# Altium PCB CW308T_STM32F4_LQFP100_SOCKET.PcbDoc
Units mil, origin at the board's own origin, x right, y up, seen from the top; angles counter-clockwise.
Board outline 2060 x 2540 mil, 2 copper layers (Top Layer, Bottom Layer); 21 components, 33 nets, 210 pads, 75 vias.
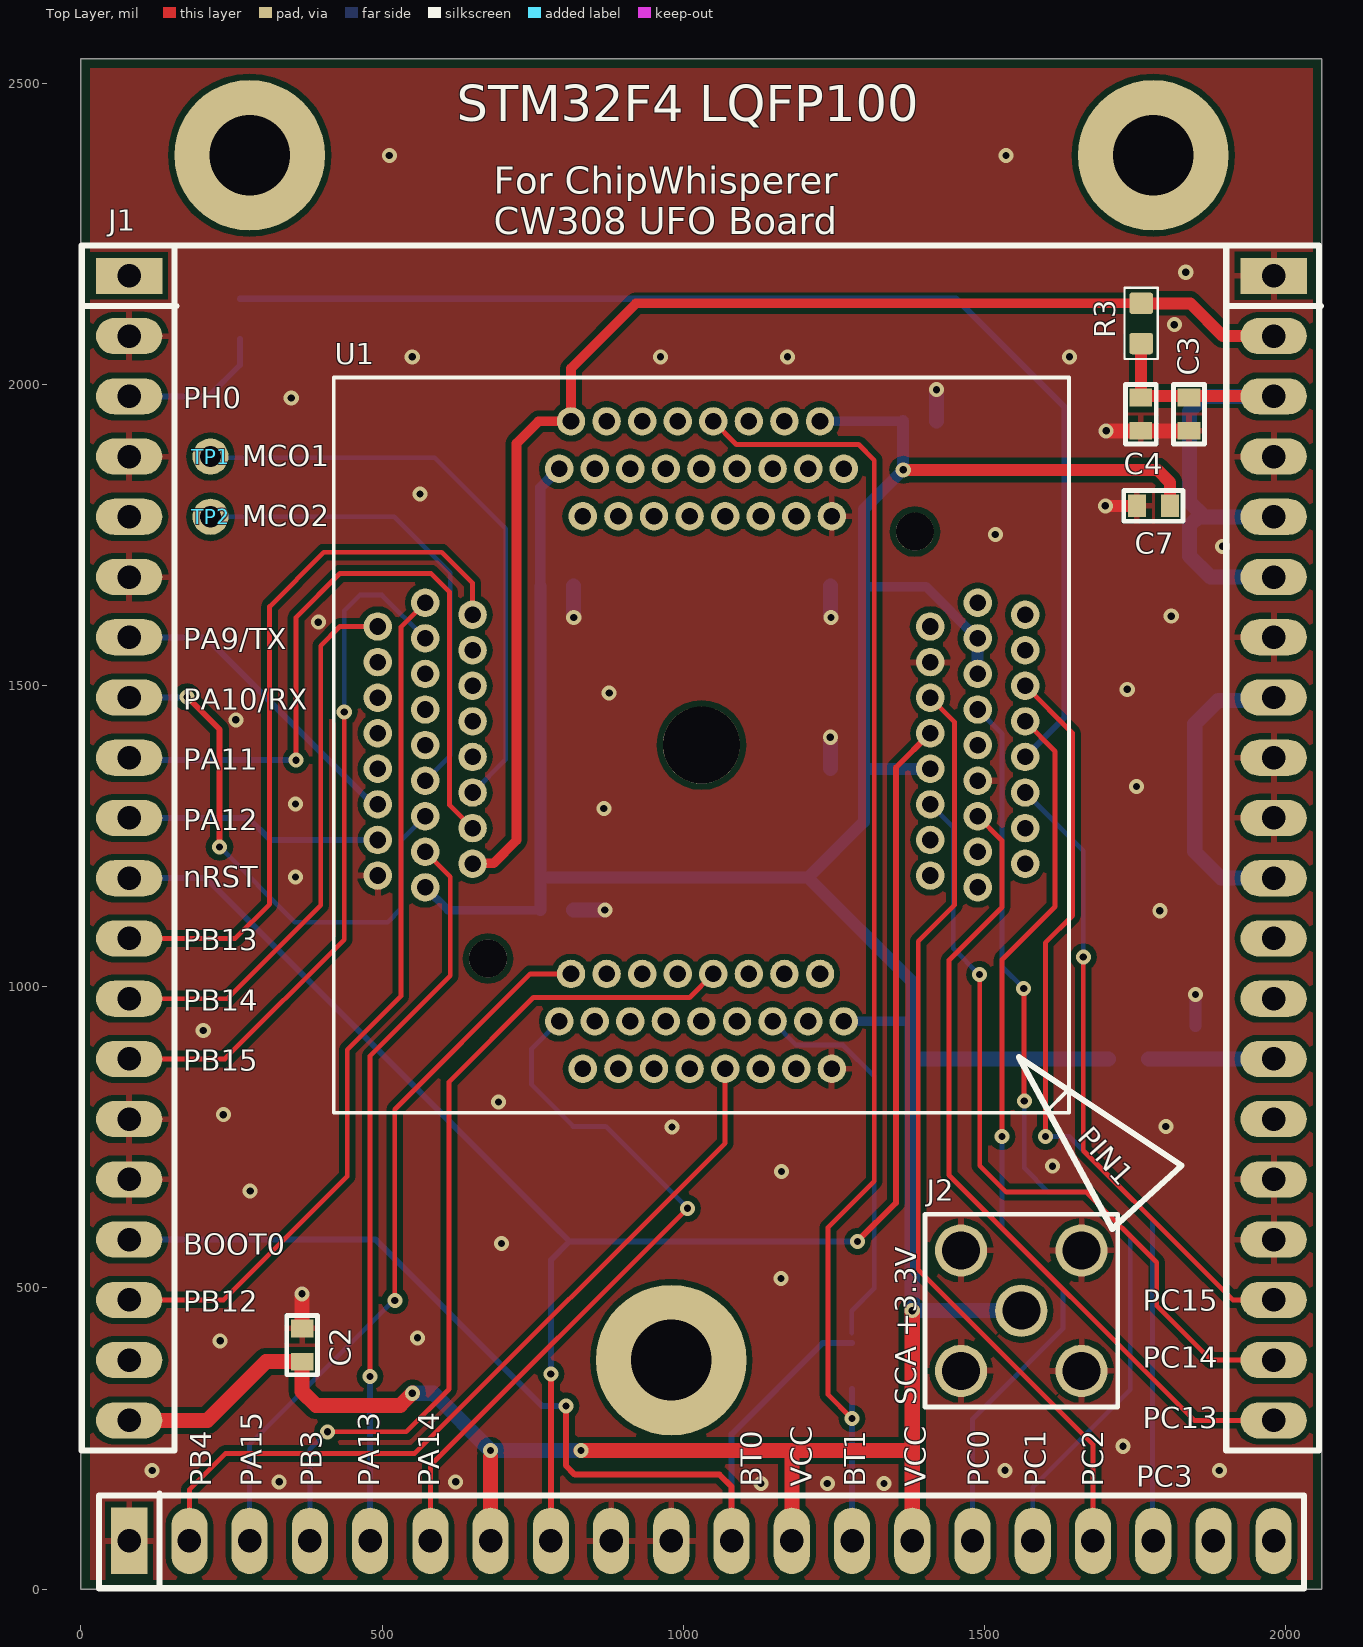
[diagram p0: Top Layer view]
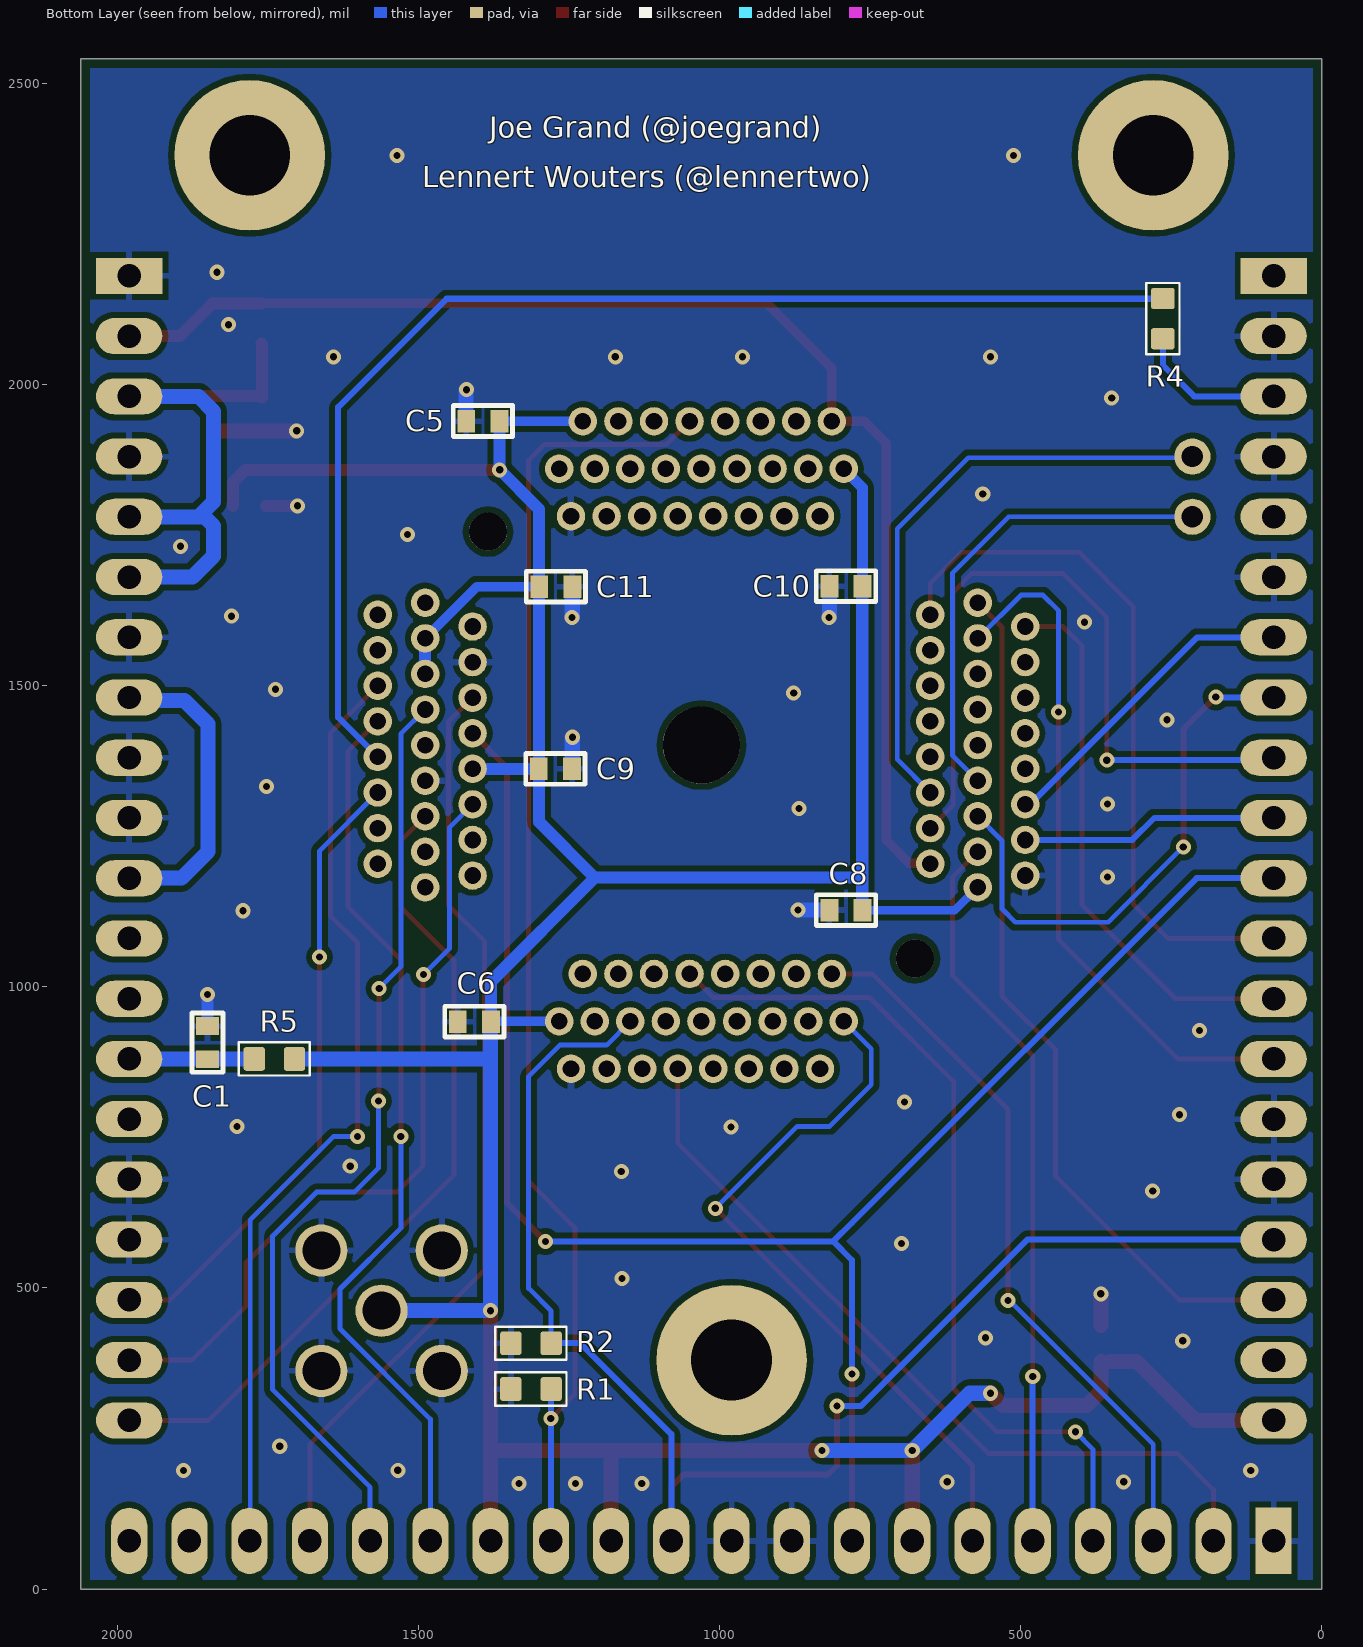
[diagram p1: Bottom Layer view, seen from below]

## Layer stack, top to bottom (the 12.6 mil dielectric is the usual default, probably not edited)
Top Solder: solder mask 0.4, Solder Resist, Dk 3.5
Top Layer: signal copper 1.4
Dielectric 1: dielectric 12.6, FR-4, Dk 4.8
Bottom Layer: signal copper 1.4
Bottom Solder: solder mask 0.4, Solder Resist, Dk 3.5

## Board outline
0,0 2060,0 2060,2540 0,2540

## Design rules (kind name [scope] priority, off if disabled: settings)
BoardOutlineClearance [All] p1: gap=15 ignorepadtopadclearanceinfootprint=FALSE except(0: Arc-SplitContinuation Track-SplitContinuation SMDPad-SplitContinuation THPad-SplitContinuation Via-SplitContinuation Fill-SplitContinuation Poly-SplitContinuation Region-SplitContinuation Text-SplitContinuation)
Clearance Clearance_1 [InPolygon] p1: gap=10 ignorepadtopadclearanceinfootprint=FALSE
Clearance [All] p2: gap=6 ignorepadtopadclearanceinfootprint=FALSE except(0: Arc-Hole Track-Hole SMDPad-Hole THPad-Hole Via-Hole Fill-Hole Poly-Hole Region-Hole Text-Hole)
HoleSize [All] p1: absolutevalues=TRUE maxlimit=200 minlimit=1 maxpercent=80.000 minpercent=20.000
MinimumSolderMaskSliver [All] p1: minsoldermaskwidth=5
PasteMaskExpansion PasteMaskExpansion_SJ [InComponent('SJ2')] p1: expansion=-200 // Disable SJ shorts
PasteMaskExpansion PasteMaskExpansion_TQFP [InComponent('U1')] p2: expansion=-1.5
PasteMaskExpansion [All] p3: expansion=0
PlaneConnect PlaneConnect_viaDirect [IsVia] p1: planeconnectstyle=Direct reliefexpansion=20 reliefentries=4 reliefconductorwidth=10 reliefairgap=10
PlaneConnect [All] p2: planeconnectstyle=Relief reliefexpansion=20 reliefentries=4 reliefconductorwidth=10 reliefairgap=10
PolygonConnect PolygonConnect_viaDirect [All vs isVia] p1: connectstyle=Direct reliefconductorwidth=10 reliefentries=4 polygonreliefangle="90 Angle" airgapwidth=10
PolygonConnect [All] p2: connectstyle=Relief reliefconductorwidth=10 reliefentries=4 polygonreliefangle="90 Angle" airgapwidth=10
RoutingVias [All] p1: holewidth=12 width=25 viastyle="Through Hole" minholewidth=12 minwidth=25 maxholewidth=28 maxwidth=50
SilkToSilkClearance [All] p1: silktosilkclearance=5
SilkToSolderMaskClearance [IsPad] p1: minsilkscreentomaskgap=2.9 clearancetoexposedcopper=TRUE
SolderMaskExpansion [All] p1: expansion=4 istentingtop=FALSE
SupplyNets "Schematic Supply Nets_1" [InNet('VCC')] p1: voltage=0.000
SupplyNets "Schematic Supply Nets" [InNet('GND')] p2: voltage=0.000
Width [All] p1: maxlimit=100 minlimit=6 preferedwidth=8 minimp=50.000000 maximp=50.000000 favimp=50.000000
24 further rules are at their usual default settings.

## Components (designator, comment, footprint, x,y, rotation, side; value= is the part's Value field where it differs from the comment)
C1 "100n" CAPC0603_M 1850,907 r90 bottom
C2 "100n" CAPC0603_M 367,405 r90 top
C3 "2u2" CAPC0603_M 1839.44,1950.25 r270 top
C4 "100n" CAPC0603_M 1759.44,1950.25 r270 top
C5 "100n" CAPC0603_M 1393,1939 r0 bottom
C6 "100n" CAPC0603_M 1407,942 r0 bottom
C7 "100n" CAPC0603_M 1780.44,1798.25 r180 top
C8 "100n" CAPC0603_M 790,1127 r0 bottom
C9 "100n" CAPC0603_M 1272.37,1361.63 r180 bottom
C10 "100n" CAPC0603_M 790,1665 r0 bottom
C11 "100n" CAPC0603_M 1271.81,1664.18 r180 bottom
J1 "CW308_TARGETCON" CW308_TBOARD_CONN 80,2180 r0 top locked
J2 "32K101-400L5" 32K101-400L5 1561,462 r0 top
R1 "10k" RESC1608X55N 1313,332 r0 bottom
R2 "10k" RESC1608X55N 1313,408 r0 bottom
R3 "10R" RESC1608X55N 1760,2101 r270 top
R4 "51R" RESC1608X55N 264,2109 r270 bottom value=100R
R5 "10R" RESC1608X55N 1739,880 r180 bottom
TP1 "TESTPOINT" TESTPOINT#1 215,1881 r0 top
TP2 "TESTPOINT" TESTPOINT#2 215,1780 r0 top
U1 "ALLSOCKET QFP100-0.5-STP" ALLSOCKET-QFP100 1030,1401 r0 top locked

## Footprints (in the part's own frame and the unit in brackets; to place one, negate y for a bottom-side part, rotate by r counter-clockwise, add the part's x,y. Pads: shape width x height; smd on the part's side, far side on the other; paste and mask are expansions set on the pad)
32K101-400L5 [mm] "Connector, SMA Jack, Vertical, 50 ohm, PCB mount"
  round 2.2 hole 1.6: 1(0,0) MP(-2.54,-2.54) MP(-2.54,2.54) MP(2.54,-2.54) MP(2.54,2.54)
  silkscreen extent -4.06,-4.06 4.06,4.06
ALLSOCKET-QFP100 [mm] "Thin QFP, 100-Leads, Body 14x14mm, Pitch 0.5mm, IPC Medium Density"
  round 1.2 hole 0.7 paste-2539.97 mask+0: 1(11.65,-6) 2(9.65,-5.5) 3(13.65,-5) 4(11.65,-4.5) 5(9.65,-4) 6(13.65,-3.5) 7(11.65,-3) 8(9.65,-2.5) 9(13.65,-2) 10(11.65,-1.5) 11(9.65,-1) 12(13.65,-0.5) 13(11.65,0) 14(9.65,0.5) 15(13.65,1) 16(11.65,1.5) 17(9.65,2) 18(13.65,2.5) 19(11.65,3) 20(9.65,3.5) 21(13.65,4) 22(11.65,4.5) 23(9.65,5) 24(13.65,5.5) 25(11.65,6) 26(6,11.65) 27(5.5,9.65) 28(5,13.65) 29(4.5,11.65) 30(4,9.65) 31(3.5,13.65) 32(3,11.65) 33(2.5,9.65) 34(2,13.65) 35(1.5,11.65) 36(1,9.65) 37(0.5,13.65) 38(0,11.65) 39(-0.5,9.65) 40(-1,13.65) 41(-1.5,11.65) 42(-2,9.65) 43(-2.5,13.65) 44(-3,11.65) 45(-3.5,9.65) 46(-4,13.65) 47(-4.5,11.65) 48(-5,9.65) 49(-5.5,13.65) 50(-6,11.65) 51(-11.65,6) 52(-9.65,5.5) 53(-13.65,5) 54(-11.65,4.5) 55(-9.65,4) 56(-13.65,3.5) 57(-11.65,3) 58(-9.65,2.5) 59(-13.65,2) 60(-11.65,1.5) 61(-9.65,1) 62(-13.65,0.5) 63(-11.65,0) 64(-9.65,-0.5) 65(-13.65,-1) 66(-11.65,-1.5) 67(-9.65,-2) 68(-13.65,-2.5) 69(-11.65,-3) 70(-9.65,-3.5) 71(-13.65,-4) 72(-11.65,-4.5) 73(-9.65,-5) 74(-13.65,-5.5) 75(-11.65,-6) 76(-6,-11.65) 77(-5.5,-9.65) 78(-5,-13.65) 79(-4.5,-11.65) 80(-4,-9.65) 81(-3.5,-13.65) 82(-3,-11.65) 83(-2.5,-9.65) 84(-2,-13.65) 85(-1.5,-11.65) 86(-1,-9.65) 87(-0.5,-13.65) 88(0,-11.65) 89(0.5,-9.65) 90(1,-13.65) 91(1.5,-11.65) 92(2,-9.65) 93(2.5,-13.65) 94(3,-11.65) 95(3.5,-9.65) 96(4,-13.65) 97(4.5,-11.65) 98(5,-9.65) 99(5.5,-13.65) 100(6,-11.65)
  round 3.25 hole 3.25 paste-2539.97 mask+0: Un1(0,0)
  round 1.6 hole 1.6 paste-2539.97 mask+0: Un2(9,9) Un3(-9,-9)
  silkscreen extent -15.5,-15.5 15.5,15.5
CAPC0603_M [mm]
  rect 0.75x0.95 smd: 1(-0.7,0) 2(0.7,0)
  silkscreen extent -1.25,-0.65 1.25,0.65, body extent -0.85,-0.45 0.85,0.45, height 0.9
CW308_TBOARD_CONN [mil]
  rect 110x60 hole 39: A1(0,0) C1(1900,0)
  oval 110x60 hole 39: A2(0,-100) A3(0,-200) A4(0,-300) A5(0,-400) A6(0,-500) A7(0,-600) A8(0,-700) A9(0,-800) A10(0,-900) A11(0,-1000) A12(0,-1100) A13(0,-1200) A14(0,-1300) A15(0,-1400) A16(0,-1500) A17(0,-1600) A18(0,-1700) A19(0,-1800) A20(0,-1900) C2(1900,-100) C3(1900,-200) C4(1900,-300) C5(1900,-400) C6(1900,-500) C7(1900,-600) C8(1900,-700) C9(1900,-800) C10(1900,-900) C11(1900,-1000) C12(1900,-1100) C13(1900,-1200) C14(1900,-1300) C15(1900,-1400) C16(1900,-1500) C17(1900,-1600) C18(1900,-1700) C19(1900,-1800) C20(1900,-1900)
  rect 60x110 hole 39: B1(0,-2100)
  oval 60x110 hole 39: B2(100,-2100) B3(200,-2100) B4(300,-2100) B5(400,-2100) B6(500,-2100) B7(600,-2100) B8(700,-2100) B9(800,-2100) B10(900,-2100) B11(1000,-2100) B12(1100,-2100) B13(1200,-2100) B14(1300,-2100) B15(1400,-2100) B16(1500,-2100) B17(1600,-2100) B18(1700,-2100) B19(1800,-2100) B20(1900,-2100)
  round 250 hole 134: MH1(200,200) MH2(1700,200) MH3(900,-1800)
  silkscreen extent -79,-2179 1979,50, body extent -50,-2149 1950,50, height 48
RESC1608X55N [mm] "Chip Resistor, Body 1.6x0.8mm, EIA 0603, IPC Medium Density"
  round 0.254 on Mech15: 0(0,0)
  rrect25% 0.9x1 smd: 1(-0.85,0) 2(0.85,0)
  Top Layer pour cut-out: -0.6,0.5 -0.4,0.7 0.4,0.7 0.6,0.5 0.6,-0.5 0.4,-0.7 -0.4,-0.7 -0.6,-0.5
  silkscreen extent -1.5,-0.7 1.5,0.7, body extent -0.87,-0.47 0.88,0.48, height 0.54
TESTPOINT#1 [mil]
  round 60 hole 35.43: 1(0,-1)
TESTPOINT#2 [mil]
  round 60 hole 35.43: 1(0,0)

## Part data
C1 C2 C4 C5 C6 C7 C8 C9 C10 C11: library part CCHIP-100n-0603, "100n, 0603", Case-EIA=0603, Case-Metric=1608
C3: library part CCHIP-2u2-0603, "2u2, 0603", Case-EIA=0603, Case-Metric=1608
J1: library part CW308_TBOARD, "CW308 \"Standard\" Target Board Connector"
J2: library part 32K145-400L5, "SMA Right Angle Jack, Edge Mount, Up to 18 GHz, -55 to 155 degC"
R1 R2: library part RCHIP-10K-0603, "10k res, 0603, 1%, 1/10W", Case-EIA=0603, Case-Metric=1608, Manufacture 1=Yageo, Manufacture Part Number 1=RC0603FR-0710KL, Rated Power=0.1W, Rated Voltage=75VDC, Supplier Part Number 1=311-10.0KHRCT-ND, Temperature Range="-55C to 155C", Tolerance=1%
R3 R5: library part RCHIP-10R-0603, "10R res, 0603, 1%, 1/10W", Case-EIA=0603, Case-Metric=1608, Manufacture 1=Yageo, Manufacture Part Number 1=RC0603FR-0710RL, Rated Power=0.1W, Rated Voltage=75VDC, Supplier Part Number 1=311-10.0HRCT-ND, Temperature Range="-55C to 155C", Tolerance=1%
R4: library part RCHIP-100R-0603, "100R res, 0603, 1%, 1/10W", Case-EIA=0603, Case-Metric=1608, Manufacture 1=Yageo, Manufacture Part Number 1=RC0603FR-07100RL, Rated Power=0.1W, Rated Voltage=75VDC, Supplier Part Number 1=311-100HRCT-ND, Temperature Range="-55C to 155C", Tolerance=1%
U1: library part STM32F427VIT6, "ARM Cortex-M4 32-bit MCU+FPU, 210 DMIPS, 2048 kB Flash, 256 kB Internal RAM, 82 I/Os, 100-pin LQFP, -40 to 85 degC, Tray", I/Os (High Current)=82, Manufacturer=STMicroelectronics, Operating Frequency(F) (Processor speed) (MHz)=168, Supplier Part Number 1=497-14049-ND, Supply Voltage(Vcc) max (V)=3.6, Supply Voltage(Vcc) min (V)=1.8

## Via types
v1: diameter 25, hole 12, Top Layer to Bottom Layer, tented both sides, 75 vias

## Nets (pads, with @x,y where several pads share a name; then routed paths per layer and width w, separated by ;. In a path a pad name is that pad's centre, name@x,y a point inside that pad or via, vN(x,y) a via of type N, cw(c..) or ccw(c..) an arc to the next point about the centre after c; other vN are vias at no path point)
BOOT0: J1.A17 J1.B11 R2.1 U1.94 | length 2405.1
  Top Layer w10: v1(805,304) 805,205 820,190 1060,190 1080,170 J1.B11
  Bottom Layer w8: U1.94 1187.45,903 1265,903 1317,851 1317,499 1279.54,461.54 R2.1@1279.54,425
  Bottom Layer w10: J1.A17 489,580 765,304 v1(805,304) ; J1.B11 1080,224 1080,257 1231,408 R2.1
BOOT1: J1.B13 R1.1 U1.37 | length 2185.5
  Top Layer w8: U1.37 1088.09,1900 1291,1900 1317,1874 1317,677 1240,600 1240,323 v1(1280,283)
  Bottom Layer w10: J1.B13 R1.1@1280,332
CLKI: R4.1 U1.12 | length 2051.4
  Bottom Layer w10: R4.1@264,2142 1453,2142 1633,1962 1633,1446.91 U1.12
CS: J1.A18 U1.51 | length 1452.7
  Top Layer w8: J1.A18 237,480 442,685 442,895 531,984 531,1596.88 U1.51
GND: C1.2 C2.2 C3.2 C4.2 C5.2 C6.2 C7.2 C8.2 C9.2 C10.2 C11.2 J1.A2 J1.A4 J1.A6 J1.A15 J1.A16 J1.B1 J1.B9 J1.B10 J1.C1 J1.C4 J1.C7 J1.C9 J1.C10 J1.C16 J1.C17 J2.MP R1.2 R2.2 U1.10 U1.20 U1.27 U1.74 U1.99 | length 552.7
  Top Layer w20: v1(1700.44,1798.25) C7.2
  Top Layer w25: C2.2@367,437.56 v1(367,490) ; v1(1701.88,1922.69) C4.2 C3.2
  Bottom Layer w20: C1.2 v1(1850,987)
  Bottom Layer w25: C8.2 v1@869.12,1127 ; v1@817.56,1613.44 C10.2 ; C9.2@1244.44,1362 v1@1244.44,1413.56 ; v1@1244.44,1613.44 C11.2@1244.44,1665 ; C5.2 v1@1420.56,1990.56
  other v1: 1129,175 1239,175 1333,175 329,178 622,178 118.11,196.85 1534,197 1889.76,196.85 1730,237 231,412 558.56,417 1161.91,515.58 697.91,573.58 280.91,660.58 1163,693 1613,702 981,767 1801,768 236.22,787.4 692.91,808.58 203,927 1791,1126 869.56,1127.44 356,1182 867.91,1295.58 356,1303 1752.23,1332.39 1244,1414 257,1443 876.91,1487.58 1736.91,1493.58 394,1605 818,1613 1244.88,1613 1810,1615 1895,1731 1517.91,1750.58 563,1818 349,1977 1420.12,1991 549.91,2045.58 961.91,2045.58 1172.91,2045.58 1640.91,2045.58 1815,2099 1834,2186 511.81,2380 1535.43,2380
GPIO3: J1.A9 U1.70 | length 1221.3
  Top Layer w8: v1(357,1376) 357,1613 430,1686 581,1686 612,1655 612,1480 612,1301.28 U1.70
  Bottom Layer w10: J1.A9 84,1376 v1(357,1376)
GPIO4: J1.A10 U1.71 | length 427.7
  Bottom Layer w10: J1.A10 278,1280 314.48,1243.52 U1.71
LED1: J1.C18 U1.9 | length 1053
  Top Layer w8: v1(1664,1049) 1664,728 1832,560 1912,480 J1.C18
  Bottom Layer w8: U1.9 1664,1225.66 v1(1664,1049)
LED2: J1.C19 U1.8 | length 1297.3
  Top Layer w8: v1@1492,1020 1492,703 1536,659 1669,659 1786,542 1786,470 1876,380 J1.C19
  Bottom Layer w8: U1.8 1448,1264.5 1448,1063.48 v1(1491.48,1020)
LED3: J1.C20 U1.7 | length 1356.6
  Top Layer w8: U1.7 1529,1242.55 1529,1132 1441,1044 1441,687 1848,280 J1.C20
MCO1: TP1.1 U1.67 | length 999.4
  Bottom Layer w8: TP1.1@215,1878 587,1878 705,1760 705,1377.18 U1.67
MCO2: TP2.1 U1.66 | length 798.8
  Bottom Layer w8: TP2.1 520,1780 613,1687 613,1383.61 U1.66
MISO: J1.A13 U1.53 | length 921
  Top Layer w8: J1.A13 243,980 398,1135 398,1566 429.85,1597.85 U1.53
MOSI: J1.A14 U1.54 | length 1159.9
  Top Layer w8: J1.A14 239,880 437,1078 v1(437,1456)
  Bottom Layer w8: v1(437,1456) 437,1624 463,1650 499.5,1650 U1.54
NetC1_1: C1.1 J1.C14 R5.1 | length 207.5
  Bottom Layer w25: R5.1 J1.C14
NetC3_1: C3.1 C4.1 J1.C3 J1.C5 J1.C6 R3.2 | length 961.4
  Top Layer w20: C4.1 C4.1@1759.44,1980.25 ; R3.2 1759.44,2066.98 C4.1@1759.44,1980.25 ; J1.C3@1944.44,1980.25 C4.1@1759.44,1980.25
  Bottom Layer w25: J1.C6 1875,1680 1840,1715 1840,1765 1855,1780 1865,1780 ; J1.C5 1865,1780 ; J1.C3 1865,1980 1840,1955 1840,1805 1865,1780
NetJ1_A3: J1.A3 R4.2 | length 249.1
  Bottom Layer w10: J1.A3 212,1980 264,2032 R4.2
NetJ1_C2: J1.C2 R3.1 U1.49 U1.73 | length 2175.4
  Top Layer w16: U1.73 650.72,1204.79 684.79,1204.79 723,1243 723,1902 759.4,1938.4 U1.49 813.46,2026.46 921.46,2134.46 R3.1
  Top Layer w20: R3.1 1841.54,2134.46 1896,2080 J1.C2
NetJ1_C8: J1.C8 J1.C11 | length 510.5
  Bottom Layer w25: J1.C11 1893,1180 1849,1224 1849,1436 1888,1475 1975,1475 J1.C8
nRST: J1.A11 J1.B8 U1.14 | length 2862.4
  Top Layer w10: J1.B8 v1(780,357) ; v1(1289,577) 1353,641 1353,1363.76 U1.14
  Bottom Layer w10: J1.A11 208,1180 780,608 811,577 ; v1(780,357) 780,546 811,577 ; v1(1289,577) 811,577
PC0: J1.B15 U1.15 | length 1521.3
  Top Layer w8: v1(1529,751) 1529,1044.98 1617,1132.98 1617,1390.77 U1.15
  Bottom Layer w8: J1.B15 1480,282 1630,432 1630,498 1529,599 v1(1529,751)
PC1: J1.B16 U1.16 | length 1588.6
  Top Layer w8: v1@1565.52,810 v1@1565.52,997
  Bottom Layer w8: U1.16 1529,1419.72 1529,1033 v1(1565,997) ; v1(1566,810) 1566,699 1606,659 1669,659 1742,586 1742,331 1580,169 J1.B16
PC2: J1.B17 U1.17 | length 1561.3
  Top Layer w8: U1.17 1450,1439.66 1450,1135 1390,1075 1390,530 1680,240 J1.B17
PC3: J1.B18 U1.18 | length 1568.2
  Top Layer w8: U1.18 1646,1420.83 1646,1118 1601,1073 v1(1601,751)
  Bottom Layer w8: v1(1601,751) 1641,751 1779,613 1779,81 J1.B18
RX: J1.A8 U1.69 | length 900.3
  Top Layer w10: v1(176,1481) 230,1427 v1(230,1232)
  Bottom Layer w8: v1(230,1232) 355,1107 509,1107 531,1129 531,1242.55 U1.69
  Bottom Layer w10: J1.A8 175,1480 v1(176,1481)
SCK: J1.A12 U1.52 | length 1198.5
  Top Layer w8: J1.A12 256,1080 313,1137 313,1631 403,1721 599,1721 650.08,1669.92 U1.52
TCK: J1.B6 U1.76 | length 1197.1
  Top Layer w8: J1.B6 580,205 v1(1007,632)
  Bottom Layer w8: U1.76 748,896.56 748,837 817,768 871,768 v1(1007,632)
TDI: J1.B3 U1.77 | length 1202.7
  Top Layer w8: v1(521,479) 521,796 746.08,1021.08 U1.77
  Bottom Layer w8: J1.B3 280,240 519,479 v1(521,479)
TDO: J1.B4 U1.89 | length 1447.3
  Top Layer w8: v1(409,261) 540,261 611,332 611,842 751,982 1010.61,982 U1.89
  Bottom Layer w8: J1.B4 380,232 v1(409,261)
TMS: J1.B5 U1.72 | length 1216.2
  Top Layer w8: v1(480,353) 480,885 613,1018 613,1182.17 U1.72
  Bottom Layer w10: J1.B5 v1(480,353)
TRST: J1.B2 U1.90 | length 1335.9
  Top Layer w8: J1.B2 180,165 240,225 554,225 1069.37,740.37 U1.90
TX: J1.A7 U1.68 | length 529.6
  Top Layer w10: J1.A7 J1.A7@85,1575
  Bottom Layer w10: J1.A7@85,1580 207,1580 484.43,1302.57 U1.68
VCC: C2.1 C5.1 C6.1 C7.1 C8.1 C9.1 C10.1 C11.1 J1.A20 J1.B7 J1.B12 J1.B14 J2.1 R5.2 U1.11 U1.19 U1.22 U1.28 U1.50 U1.75 U1.100 | length 6755.9
  Top Layer w20: v1(1365,1858) 1787,1858 1808,1837 C7.1
  Top Layer w25: J1.A20 210,280 307.44,377.44 C2.1@352.56,377.44 ; C2.1 367,328 390,305 530,305 v1(550,325) ; J1.B7 v1@680,220 ; v1(830,230) 1180,230 ; J1.B12 1180,230 ; J1.B14 1380,230 ; v1(1380,462) 1380,230 ; 1180,230 1380,230
  Bottom Layer w14: U1.75 609.12,1127 C8.1@761.13,1127
  Bottom Layer w16: U1.28 C5.1@1365,1938.4 ; U1.100 C6.1@1379.44,942.34 ; C11.1@1299.56,1665 1299.56,1664 1402.83,1664 U1.22
  Bottom Layer w18: C10.1 762.44,1828.32 U1.50
  Bottom Layer w20: C8.1 763,1127.56 763,1181 ; C10.1@763,1665 763,1181 ; C11.1@1299.56,1664 C9.1@1299.56,1362 ; C11.1@1299.56,1665 1299.56,1792.56 v1(1365,1858) 1365,1938.4 C5.1@1365,1939 ; C6.1@1379.44,942.34 1379.44,1008.56 1207,1181 ; U1.11 C9.1 C9.1@1299.56,1362 ; U1.19 U1.22 ; 763,1181 1207,1181 ; 1207,1181 1299.56,1273.56 C9.1@1299.56,1362
  Bottom Layer w25: v1(550,325) 585,325 v1(680,230) v1(830,230) ; C6.1@1380,942 1380,880 ; J2.1 v1(1380,462) 1380,880 ; R5.2 1380,880
pads on no net: J1.A1 J1.A5 J1.A19 J1.B19 J1.B20 J1.C12 J1.C13 J1.C15 J1.MH1 J1.MH2 J1.MH3 R1.0 R2.0 R3.0 R4.0 R5.0 U1.1 U1.2 U1.3 U1.4 U1.5 U1.6 U1.13 U1.21 U1.23 U1.24 U1.25 U1.26 U1.29 U1.30 U1.31 U1.32 U1.33 U1.34 U1.35 U1.36 U1.38 U1.39 U1.40 U1.41 U1.42 U1.43 U1.44 U1.45 U1.46 U1.47 U1.48 U1.55 U1.56 U1.57 U1.58 U1.59 U1.60 U1.61 U1.62 U1.63 U1.64 U1.65 U1.78 U1.79 U1.80 U1.81 U1.82 U1.83 U1.84 U1.85 U1.86 U1.87 U1.88 U1.91 U1.92 U1.93 U1.95 U1.96 U1.97 U1.98 U1.Un1 U1.Un2 U1.Un3

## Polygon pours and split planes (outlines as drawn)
GND on Top Layer "Top Layer-GND" (solid, remove dead copper, pour order 2): -30,2660 -10,2640 2100,2640 2100,-25 2120,-45 2100,-65 -50,-65
GND on Bottom Layer "GNDBOT" (solid, remove dead copper, pour order 0): -35,2580 -75,2540 -75,-70 2095,-70 2175,10 2175,2675

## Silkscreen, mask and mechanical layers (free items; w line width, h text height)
Top Overlay:
  lines w10: 155,2230 1901.26,2230 ; 1557,883 1827,703 1712,598 1557,883
  text "STM32F4 LQFP100" at 624,2437 h60
  text "For ChipWhisperer / CW308 UFO Board" at 685,2249 h45
  text "PH0" at 170,1960 h35
  text "MCO1" at 268,1864 h35
  text "MCO2" at 268,1764 h35
  text "PA9/TX" at 170,1560 h35
  text "PA10/RX" at 170,1460 h35
  text "PA11" at 170,1360 h35
  text "PA12" at 170,1260 h35
  text "nRST" at 170,1165 h35
  text "PB13" at 170,1060 h35
  text "PB14" at 170,960 h35
  text "PB15" at 170,860 h35
  text "PIN1" at 1652,748 h35 r311.73
  text "BOOT0" at 170,555 h35
  text "PC15" at 1763,462 h35
  text "PB12" at 170,460 h35
  text "PC14" at 1763,367 h35
  text "SCA +3.3V" at 1387,305 h35 r90
  text "PC13" at 1763,267 h35
  text "PB4" at 216,170 h35 r90
  text "PA15" at 300,170 h35 r90
  text "PB3" at 400,170 h35 r90
  text "PA13" at 495,170 h35 r90
  text "PA14" at 595,170 h35 r90
  text "BT0" at 1130,170 h35 r90
  text "VCC" at 1213,170 h35 r90
  text "BT1" at 1302,170 h35 r90
  text "VCC" at 1402,170 h35 r90
  text "PC0" at 1507,170 h35 r90
  text "PC1" at 1602,170 h35 r90
  text "PC2" at 1697,170 h35 r90
  text "PC3" at 1752,170 h35
Bottom Overlay:
  text "Joe Grand (@joegrand)" at 1382.5,2409 h35
  text "Lennert Wouters (@lennertwo)" at 1493.3,2327 h35
Mechanical 1:
  the board outline again, w10

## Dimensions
2060,-30 to 0,-30 on Drill Drawing
-30,0 to -45,2540 on Drill Drawing
-30,0 to -45,2540 on Drill Drawing
0,-40 to 2060,-40 on Drill Drawing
